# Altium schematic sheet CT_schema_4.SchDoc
size 287 x 163 mm
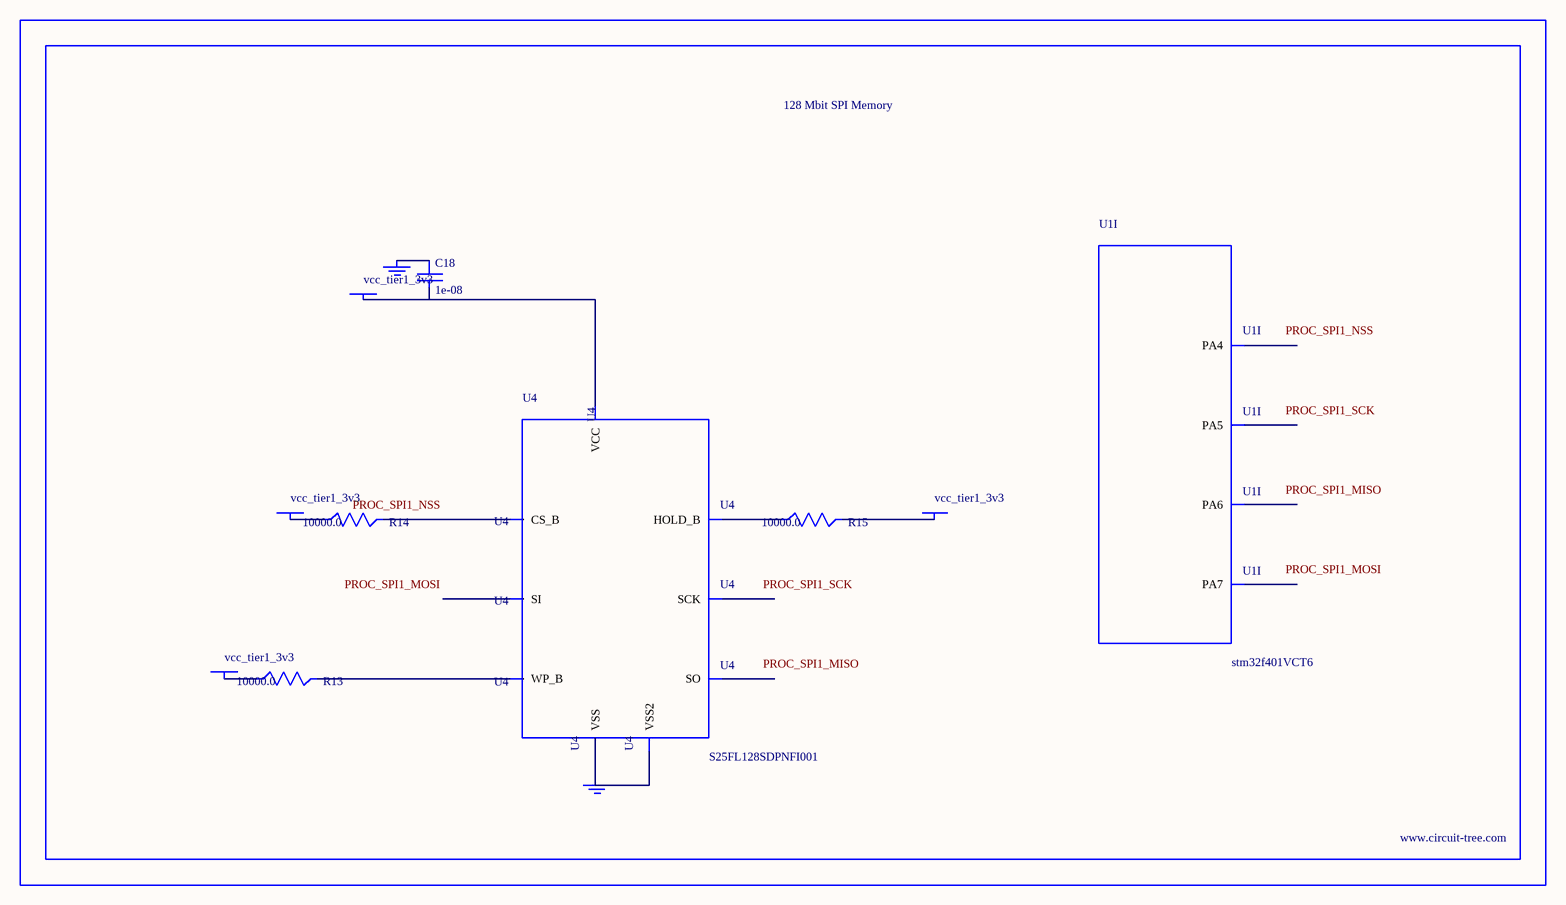
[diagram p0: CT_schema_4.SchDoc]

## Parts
BORDER3  (no value)
C18  1e-08  [C0402]
GND_INSTANCE_3_0  (no value)
GND_INSTANCE_3_1  (no value)
POWER_INSTANCE_3_0  vcc_tier1_3v3
POWER_INSTANCE_3_1  vcc_tier1_3v3
POWER_INSTANCE_3_2  vcc_tier1_3v3
POWER_INSTANCE_3_3  vcc_tier1_3v3
R13  10000.0  [R0603]
R14  10000.0  [R0603]
R15  10000.0  [R0603]
U1  stm32f401VCT6  [LQFP100]  (part I of 11)
U4  S25FL128SDPNFI001  [WNG008]

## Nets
NetC18_1: C18.1 GND_INSTANCE_3_0.0(GND)
NetC18_2: C18.2 POWER_INSTANCE_3_3.0(PWR) U4.8(VCC)
NetGND_INSTANCE_3_1_0: GND_INSTANCE_3_1.0(GND) U4.4(VSS) U4.PAD(VSS2)
NetPOWER_INSTANCE_3_0_0: POWER_INSTANCE_3_0.0(PWR) R14.1
NetPOWER_INSTANCE_3_1_0: POWER_INSTANCE_3_1.0(PWR) R13.1
NetPOWER_INSTANCE_3_2_0: POWER_INSTANCE_3_2.0(PWR) R15.2
NetR13_2: R13.2 U4.3(WP_B)
NetR14_2: R14.2 U4.1(CS_B)
NetR15_1: R15.1 U4.7(HOLD_B)

Not connected (* = marked no-connect by the designer): U1 29(PA4) 30(PA5) 31(PA6) 32(PA7); U4 2(SO) 5(SI) 6(SCK)

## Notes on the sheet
- Labels drawn without touching a wire or pin: PROC_SPI1_MISO, PROC_SPI1_MOSI, PROC_SPI1_NSS, PROC_SPI1_SCK

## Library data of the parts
BORDER3 = BORDER_PAGE3
C18 = C0402C103K3RAC
GND_INSTANCE_3_0 GND_INSTANCE_3_1 = GND
POWER_INSTANCE_3_0-POWER_INSTANCE_3_3 = PWR
R13-R15 = RC0603JR-0710KL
